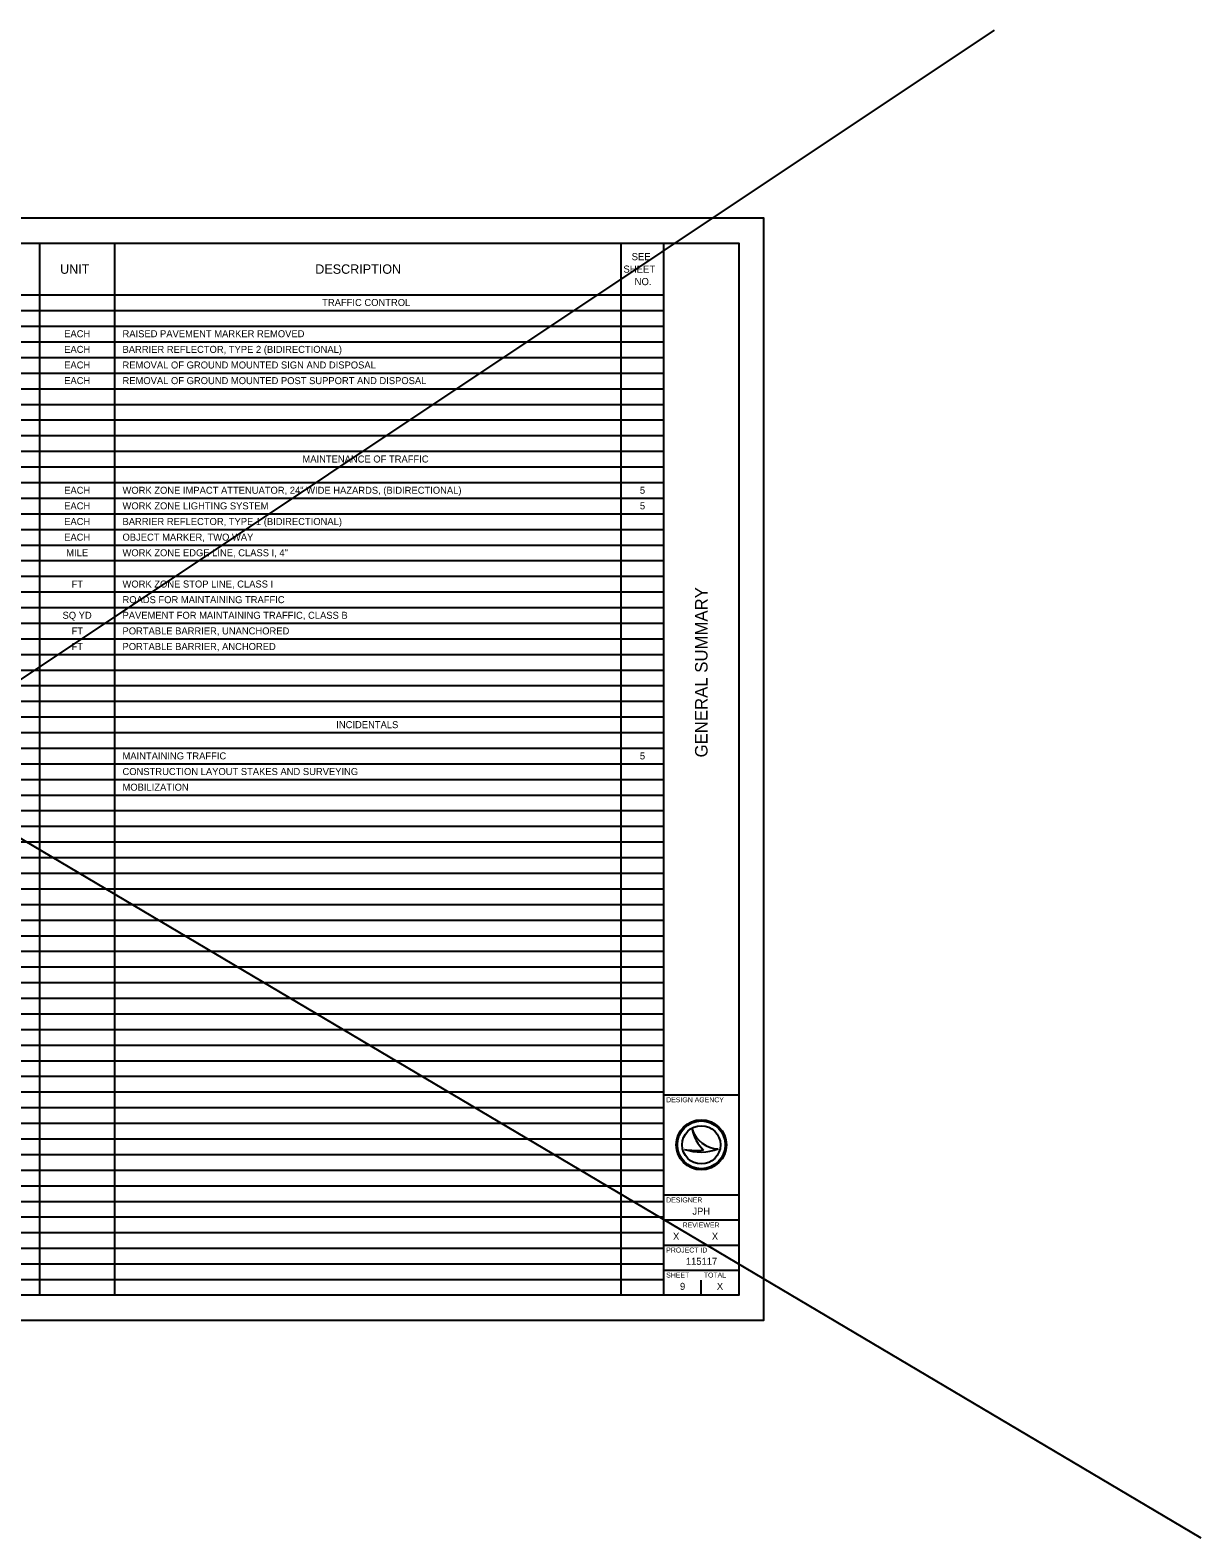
# Model space of a CAD drawing. Extents: x 0 to 93.7, y -7 to 23.1.
# Drawn here: x 70.33 to 93.69, y -7 to 23.1 of the extents above; entities that cross this region are included whole.
import ezdxf

# ---------------------------------------------------------------- set-up
doc = ezdxf.new("R2010")
doc.units = 0
for name, color, linetype in [('SH_Border', 7, 'Continuous'), ('SH_Cut_Line', 7, 'Continuous'), ('SH_Data', 7, 'Continuous'), ('SH_Text', 7, 'Continuous'), ('TX_P_1', 7, 'Continuous')]:
    doc.layers.add(name, color=color, linetype=linetype)

msp = doc.modelspace()

# ---------------------------------------------------------------- linework, layer by layer
at = {"layer": 'SH_Border'}
for p, q in [((82.975, -2.158), (82.975, 18.842)), ((82.975, -2.158), (82.975, 18.842)), ((82.975, 1.842), (84.475, 1.842)), ((82.975, -0.158), (84.475, -0.158)), ((82.975, -0.658), (84.475, -0.658)), ((82.975, -1.158), (84.475, -1.158)), ((82.975, -1.658), (84.475, -1.658))]:
    msp.add_line(p, q, dxfattribs=at)
msp.add_lwpolyline([(52.475, 18.842), (84.475, 18.842), (84.475, -2.158), (52.475, -2.158)], close=True, dxfattribs=at)
at = {"layer": 'SH_Cut_Line'}
msp.add_lwpolyline([(50.975, -2.658), (84.975, -2.658), (84.975, 19.342), (50.975, 19.342)], close=True, dxfattribs=at)
at = {"layer": 'SH_Data'}
for p, q in [((70.525, -2.158), (70.525, 18.842)), ((72.025, -2.158), (72.025, 18.842)), ((82.125, -2.158), (82.125, 18.842)), ((52.475, 17.81), (82.975, 17.81)), ((52.475, 17.498), (82.975, 17.498)), ((52.475, 17.186), (82.975, 17.186)), ((52.475, 16.874), (82.975, 16.874)), ((52.475, 16.562), (82.975, 16.562)), ((52.475, 16.25), (82.975, 16.25)), ((52.475, 15.938), (82.975, 15.938)), ((52.475, 15.626), (82.975, 15.626)), ((52.475, 15.314), (82.975, 15.314)), ((52.475, 15.002), (82.975, 15.002)), ((52.475, 14.69), (82.975, 14.69)), ((52.475, 14.378), (82.975, 14.378)), ((52.475, 14.066), (82.975, 14.066)), ((52.475, 13.754), (82.975, 13.754)), ((52.475, 13.442), (82.975, 13.442)), ((52.475, 13.13), (82.975, 13.13)), ((52.475, 12.818), (82.975, 12.818)), ((52.475, 12.506), (82.975, 12.506)), ((52.475, 12.194), (82.975, 12.194)), ((52.475, 11.882), (82.975, 11.882)), ((52.475, 11.57), (82.975, 11.57)), ((52.475, 11.258), (82.975, 11.258)), ((52.475, 10.946), (82.975, 10.946)), ((52.475, 10.634), (82.975, 10.634)), ((52.475, 10.322), (82.975, 10.322)), ((52.475, 10.01), (82.975, 10.01)), ((52.475, 9.698), (82.975, 9.698)), ((52.475, 9.386), (82.975, 9.386)), ((52.475, 9.074), (82.975, 9.074)), ((52.475, 8.762), (82.975, 8.762)), ((52.475, 8.45), (82.975, 8.45)), ((52.475, 8.138), (82.975, 8.138)), ((52.475, 7.826), (82.975, 7.826)), ((52.475, 7.514), (82.975, 7.514)), ((52.475, 7.202), (82.975, 7.202)), ((52.475, 6.89), (82.975, 6.89)), ((52.475, 6.578), (82.975, 6.578)), ((52.475, 6.266), (82.975, 6.266)), ((52.475, 5.954), (82.975, 5.954)), ((52.475, 5.642), (82.975, 5.642)), ((52.475, 5.33), (82.975, 5.33)), ((52.475, 5.018), (82.975, 5.018)), ((52.475, 4.706), (82.975, 4.706)), ((52.475, 4.394), (82.975, 4.394)), ((52.475, 4.082), (82.975, 4.082)), ((52.475, 3.77), (82.975, 3.77)), ((52.475, 3.458), (82.975, 3.458)), ((52.475, 3.146), (82.975, 3.146)), ((52.475, 2.834), (82.975, 2.834)), ((52.475, 2.522), (82.975, 2.522)), ((52.475, 2.21), (82.975, 2.21)), ((52.475, 1.898), (82.975, 1.898)), ((52.475, 1.586), (82.975, 1.586)), ((52.475, 1.274), (82.975, 1.274)), ((52.475, 0.962), (82.975, 0.962)), ((83.543, 1.152), (83.543, 1.152)), ((52.475, 0.65), (82.975, 0.65)), ((83.392, 0.752), (83.392, 0.752)), ((83.725, 0.842), (83.725, 0.842)), ((84.062, 0.761), (84.062, 0.761)), ((52.475, 0.338), (82.975, 0.338)), ((52.475, 0.026), (82.975, 0.026)), ((52.475, -0.286), (82.975, -0.286)), ((52.475, -0.598), (82.975, -0.598)), ((52.475, -0.91), (82.975, -0.91)), ((52.475, -1.222), (82.975, -1.222)), ((52.475, -1.534), (82.975, -1.534)), ((52.475, -1.846), (82.975, -1.846)), ((83.35, -1.983), (83.35, -1.983)), ((83.725, -2.158), (83.725, -1.858))]:
    msp.add_line(p, q, dxfattribs=at)
for radius in [0.5, 0.477, 0.477, 0.382]:
    msp.add_circle((83.725, 0.842), radius, dxfattribs=at)
for centre, radius, start, end in [((84.091, 1.34), 0.58, 198.9257, 198.9319), ((84.322, 1.312), 0.796, 191.6379, 191.6421), ((84.091, 1.34), 0.58, 198.9319, 267.1657), ((84.322, 1.312), 0.796, 191.6421, 226.0947), ((83.715, 1.712), 1.013, 251.4576, 290.0832), ((83.623, 1.997), 1.266, 259.4964, 259.4995), ((83.715, 1.712), 1.013, 251.4527, 251.4576), ((83.623, 1.997), 1.266, 259.4995, 276.6672)]:
    msp.add_arc(centre, radius, start, end, dxfattribs=at)
at = {"layer": 'SH_Text'}
for p, q in [((89.571, 23.097), (48.408, -4.366)), ((46.583, 20.932), (93.694, -7.004))]:
    msp.add_line(p, q, dxfattribs=at)

# ---------------------------------------------------------------- texts
at = {"layer": 'SH_Data'}
for s, height, p in [('UNIT', 0.1875, (70.929, 18.233)), ('DESCRIPTION', 0.1875, (76.022, 18.233)), ('SHEET', 0.1426, (82.17, 18.255)), ('SEE', 0.1426, (82.335, 18.504)), ('NO.', 0.1426, (82.394, 18.006)), ('DESIGN AGENCY', 0.1, (83.025, 1.692)), ('DESIGNER', 0.1, (83.025, -0.308)), ('JPH', 0.14, (83.548, -0.553)), ('REVIEWER', 0.1, (83.353, -0.808)), ('X', 0.14, (83.161, -1.053)), ('X', 0.14, (83.936, -1.053)), ('PROJECT ID', 0.1, (83.025, -1.308)), ('115117', 0.14, (83.418, -1.553)), ('SHEET', 0.1, (83.025, -1.808)), ('TOTAL', 0.1, (83.775, -1.808)), ('9', 0.14, (83.3, -2.053)), ('X', 0.14, (84.036, -2.053))]:
    msp.add_text(s, height=height, dxfattribs=at).set_placement(p)
msp.add_text('GENERAL SUMMARY', height=0.25, rotation=90, dxfattribs=at).set_placement((83.85, 8.577))
at = {"layer": 'TX_P_1'}
for s, p in [('TRAFFIC CONTROL', (76.16, 17.59)), ('EACH', (71.011, 16.966)), ('RAISED PAVEMENT MARKER REMOVED', (72.175, 16.966)), ('EACH', (71.011, 16.654)), ('BARRIER REFLECTOR, TYPE 2 (BIDIRECTIONAL)', (72.175, 16.654)), ('EACH', (71.011, 16.342)), ('REMOVAL OF GROUND MOUNTED SIGN AND DISPOSAL', (72.175, 16.342)), ('EACH', (71.011, 16.03)), ('REMOVAL OF GROUND MOUNTED POST SUPPORT AND DISPOSAL', (72.175, 16.03)), ('MAINTENANCE OF TRAFFIC', (75.766, 14.465)), ('EACH', (71.011, 13.841)), ('WORK ZONE IMPACT ATTENUATOR, 24" WIDE HAZARDS, (BIDIRECTIONAL)', (72.175, 13.841)), ('5', (82.5, 13.841)), ('EACH', (71.011, 13.529)), ('WORK ZONE LIGHTING SYSTEM', (72.175, 13.529)), ('5', (82.5, 13.529)), ('EACH', (71.011, 13.217)), ('BARRIER REFLECTOR, TYPE 1 (BIDIRECTIONAL)', (72.175, 13.217)), ('EACH', (71.011, 12.905)), ('OBJECT MARKER, TWO WAY', (72.175, 12.905)), ('MILE', (71.052, 12.593)), ('WORK ZONE EDGE LINE, CLASS I, 4"', (72.175, 12.593)), ('FT', (71.158, 11.969)), ('WORK ZONE STOP LINE, CLASS I', (72.175, 11.969)), ('ROADS FOR MAINTAINING TRAFFIC', (72.175, 11.657)), ('SQ YD', (70.978, 11.345)), ('PAVEMENT FOR MAINTAINING TRAFFIC, CLASS B', (72.175, 11.345)), ('FT', (71.158, 11.033)), ('PORTABLE BARRIER, UNANCHORED', (72.175, 11.033)), ('FT', (71.158, 10.721)), ('PORTABLE BARRIER, ANCHORED', (72.175, 10.721)), ('INCIDENTALS', (76.441, 9.161)), ('MAINTAINING TRAFFIC', (72.175, 8.537)), ('5', (82.5, 8.537)), ('CONSTRUCTION LAYOUT STAKES AND SURVEYING', (72.175, 8.225)), ('MOBILIZATION', (72.175, 7.913))]:
    msp.add_text(s, height=0.14, dxfattribs=at).set_placement(p)

doc.saveas('drawing.dxf')
